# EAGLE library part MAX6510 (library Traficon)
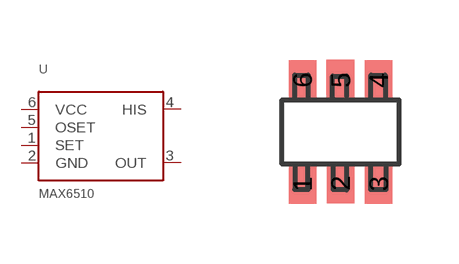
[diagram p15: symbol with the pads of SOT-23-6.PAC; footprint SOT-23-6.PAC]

Designator prefix U

## MAX6510  [SOT-23-6.PAC]
1  SET  in
2  GND  pas
3  OUT
4  HIS  in
5  OSET  in
6  VCC  pas

## Footprint SOT-23-6.PAC (pad centres in mm)
smd 0.686 x 0.991: 1 -0.953,-1.295; 2 0,-1.283; 3 0.953,-1.295; 4 0.953,1.295; 6 -0.953,1.295
smd 0.7 x 1: 5 0,1.3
